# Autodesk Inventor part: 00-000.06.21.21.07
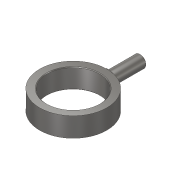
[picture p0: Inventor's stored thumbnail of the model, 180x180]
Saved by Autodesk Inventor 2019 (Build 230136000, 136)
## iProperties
Created: 2019-01
Part Number: 00-000.06.21.21.07
Material: Steel, Mild
Document SubType Name: Modeling
Designer: m.vorobev
Density: 7.85 g/cm^3
Appearance: Semi-Polished
Author: m.vorobev
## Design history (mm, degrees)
sketch "Sketch1"
  geometry: L1 (43, 16)-(55, 16); L2 (55, 16)-(55, -16); L3 (55, -16)-(43, -16); L4 (43, -16)-(43, 16); L5 (0, 0)-(19.028, 0); L6 (19.028, 0)-(19.028, 10.694); L7 (19.028, 10.694)-(0, 10.694); L8 (0, 10.694)-(0, 0); 1 further point
  constraints: 16 end point, 4 parallel, 2 horizontal, 2 perpendicular, 1 horizontal alignment, 1 midpoint
  dimensions: "d0" = 110 diameter of L2 L8; "d1" = 86 diameter of L4 L8; "d2" = 32 distance of L1.end L2.end
revolve "Revolution1" sketch "Sketch1" stored, may be unused: angle "d3" = 90 deg
chamfer "Chamfer1" distance "d4" = 1; stored, may be unused: second distance "d5" = 2, angle "d6" = 45 deg
sketch "Sketch2"
  geometry: L1 (0, -48.987)-(-10, -48.987); L2 (-10, -48.987)-(-10, -110); L3 (-10, -110)-(0, -110); L4 (0, -110)-(0, -48.987); L5 (0, -58)-(-14, -58); L6 (-14, -58)-(-14, -47.209); L7 (-14, -47.209)-(0, -47.209); L8 (0, -47.209)-(0, -58); L9 (0, 0)-(-16.492, 0); 1 further point
  constraints: 18 end point, 4 parallel, 3 horizontal, 2 perpendicular, 1 midpoint, 1 point on line, 1 vertical alignment
  dimensions: "d7" = 20 diameter of L2 L4; "d8" = 28 diameter of L6 L4; "d9" = 116 diameter of L5 L9; "d10" = 220 diameter of L3 L9
revolve "Revolution2" sketch "Sketch2" stored, may be unused: angle "d11" = 90 deg
chamfer "Chamfer2" distance "d12" = 1; stored, may be unused: second distance "d13" = 2, angle "d14" = 45 deg
body "Solid1"
